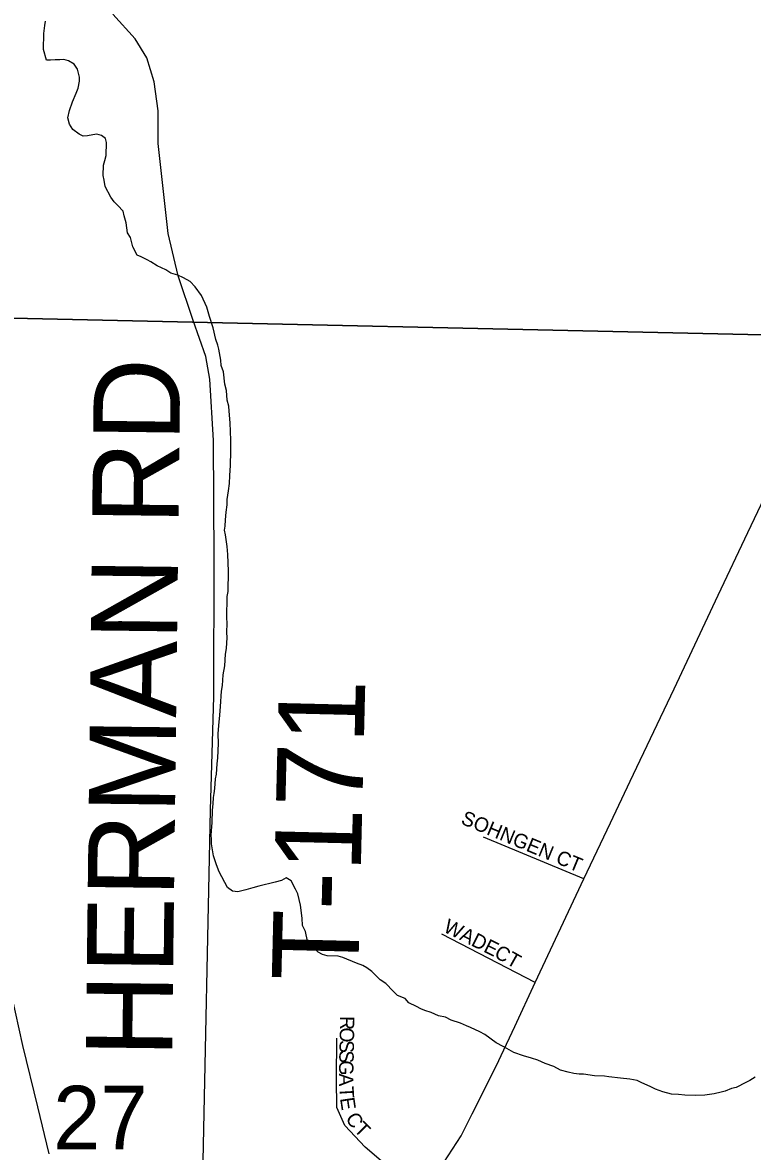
# Model space of a CAD drawing. Extents: x 0 to 34, y -2.3 to 22.
# Drawn here: x 5.852 to 6.332, y 15.821 to 16.564 of the extents above; entities that cross this region are included whole.
import ezdxf

# ---------------------------------------------------------------- set-up
doc = ezdxf.new("R2010")
doc.units = 0
for name, color, linetype in [('GM_X_Minor_River', 7, 'Continuous'), ('GM_X_Section', 7, 'Continuous'), ('GM_X_Section_Text', 7, 'Continuous'), ('GM_X_State_Route', 7, 'Continuous'), ('GM_X_Township_Road', 7, 'Continuous'), ('GM_X_Township_Road_Text', 7, 'Continuous'), ('GM_X_Township_Subdivision', 7, 'Continuous'), ('GM_X_Township_Subdivision_Text', 7, 'Continuous'), ('GM_X_US_Route', 7, 'Continuous')]:
    doc.layers.add(name, color=color, linetype=linetype)

msp = doc.modelspace()

# ---------------------------------------------------------------- linework, layer by layer
at = {"layer": 'GM_X_Minor_River'}
for p, q in [((5.86615, 16.56212), (5.86661, 16.56477)), ((5.86531, 16.54619), (5.86562, 16.55682)), ((5.86562, 16.55682), (5.86615, 16.56212)), ((5.86739, 16.53929), (5.86531, 16.54619)), ((5.87005, 16.53921), (5.86739, 16.53929)), ((5.8731, 16.5395), (5.87005, 16.53921)), ((5.87613, 16.53941), (5.8731, 16.5395)), ((5.8788, 16.53971), (5.87613, 16.53941)), ((5.88182, 16.53886), (5.8788, 16.53971)), ((5.88555, 16.53647), (5.88182, 16.53886)), ((5.88774, 16.53336), (5.88555, 16.53647)), ((5.88911, 16.52801), (5.88774, 16.53336)), ((5.88903, 16.52535), (5.88911, 16.52801)), ((5.8869, 16.51743), (5.88814, 16.52082)), ((5.88814, 16.52082), (5.88903, 16.52535)), ((5.88445, 16.51181), (5.8869, 16.51743)), ((5.88148, 16.50126), (5.88239, 16.50617)), ((5.88239, 16.50617), (5.88445, 16.51181)), ((5.8825, 16.49706), (5.88148, 16.50126)), ((5.88468, 16.49357), (5.8825, 16.49706)), ((5.88877, 16.49041), (5.88468, 16.49357)), ((5.89139, 16.48919), (5.88877, 16.49041)), ((5.89788, 16.49014), (5.89444, 16.48948)), ((5.90055, 16.49044), (5.89788, 16.49014)), ((5.90357, 16.48959), (5.90055, 16.49044)), ((5.89444, 16.48948), (5.89139, 16.48919)), ((5.90617, 16.48761), (5.90357, 16.48959)), ((5.90686, 16.48493), (5.90617, 16.48761)), ((5.90661, 16.47658), (5.90686, 16.48493)), ((5.90575, 16.47319), (5.90661, 16.47658)), ((5.90471, 16.46334), (5.90491, 16.47017)), ((5.90491, 16.47017), (5.90575, 16.47319)), ((5.90538, 16.46028), (5.90471, 16.46334)), ((5.90601, 16.45609), (5.90538, 16.46028)), ((5.90961, 16.44914), (5.90601, 16.45609)), ((5.9118, 16.44603), (5.90961, 16.44914)), ((5.9144, 16.44368), (5.9118, 16.44603)), ((5.91771, 16.43978), (5.9144, 16.44368)), ((5.91838, 16.43672), (5.91771, 16.43978)), ((5.91976, 16.43212), (5.91838, 16.43672)), ((5.92071, 16.42564), (5.91976, 16.43212)), ((5.92253, 16.42254), (5.92071, 16.42564)), ((5.92425, 16.41641), (5.92253, 16.42254)), ((5.92713, 16.41101), (5.92425, 16.41641)), ((5.92975, 16.40979), (5.92713, 16.41101)), ((5.9335, 16.40778), (5.92975, 16.40979)), ((5.93612, 16.40656), (5.9335, 16.40778)), ((5.94022, 16.40378), (5.93612, 16.40656)), ((5.94585, 16.40133), (5.94022, 16.40378)), ((5.94921, 16.39895), (5.94585, 16.40133)), ((5.95373, 16.39768), (5.94921, 16.39895)), ((5.95748, 16.39605), (5.95373, 16.39768)), ((5.96197, 16.39363), (5.95748, 16.39605)), ((5.96529, 16.39011), (5.96197, 16.39363)), ((5.9693, 16.3843), (5.96529, 16.39011)), ((5.97288, 16.37659), (5.9693, 16.3843)), ((5.9746, 16.37046), (5.97288, 16.37659)), ((5.97705, 16.36317), (5.9746, 16.37046)), ((5.97873, 16.35552), (5.97705, 16.36317)), ((5.98014, 16.35168), (5.97873, 16.35552)), ((5.98082, 16.349), (5.98014, 16.35168)), ((5.98213, 16.34175), (5.98082, 16.349)), ((5.98241, 16.33832), (5.98213, 16.34175)), ((5.98381, 16.3341), (5.98241, 16.33832)), ((5.98471, 16.32609), (5.98381, 16.3341)), ((5.98573, 16.32189), (5.98471, 16.32609)), ((5.9863, 16.31541), (5.98573, 16.32189)), ((5.98733, 16.31158), (5.9863, 16.31541)), ((5.98761, 16.30815), (5.98733, 16.31158)), ((5.98815, 16.30054), (5.98761, 16.30815)), ((5.98858, 16.28913), (5.98815, 16.30054)), ((5.98875, 16.28191), (5.98858, 16.28913)), ((5.98847, 16.27242), (5.98875, 16.28191)), ((5.98791, 16.26598), (5.98847, 16.27242)), ((5.98723, 16.25574), (5.98775, 16.26067)), ((5.98775, 16.26067), (5.98791, 16.26598)), ((5.98631, 16.25007), (5.98723, 16.25574)), ((5.98568, 16.24173), (5.98621, 16.24666)), ((5.98621, 16.24666), (5.98631, 16.25007)), ((5.98516, 16.23681), (5.98568, 16.24173)), ((5.98458, 16.22999), (5.98504, 16.23264)), ((5.98525, 16.22693), (5.98458, 16.22999)), ((5.98504, 16.23264), (5.98516, 16.23681)), ((5.98617, 16.21931), (5.98525, 16.22693)), ((5.98678, 16.21397), (5.98617, 16.21931)), ((5.98721, 16.20294), (5.98678, 16.21397)), ((5.98683, 16.18966), (5.98721, 16.20294)), ((5.98594, 16.17221), (5.98635, 16.18625)), ((5.98635, 16.18625), (5.98683, 16.18966)), ((5.98622, 16.16878), (5.98594, 16.17221)), ((5.98604, 16.16271), (5.98622, 16.16878)), ((5.98574, 16.15208), (5.98632, 16.15928)), ((5.98632, 16.15928), (5.98604, 16.16271)), ((5.98464, 16.14072), (5.98525, 16.1483)), ((5.98525, 16.1483), (5.98574, 16.15208)), ((5.98371, 16.13467), (5.98464, 16.14072)), ((5.98313, 16.12785), (5.98371, 16.13467)), ((5.98264, 16.12407), (5.98313, 16.12785)), ((5.98196, 16.11383), (5.98264, 16.12407)), ((5.98142, 16.10815), (5.98196, 16.11383)), ((5.98084, 16.10133), (5.98142, 16.10815)), ((5.9803, 16.09602), (5.98084, 16.10133)), ((5.9805, 16.08956), (5.9803, 16.09602)), ((5.98022, 16.08007), (5.9805, 16.08956)), ((5.97915, 16.06947), (5.97973, 16.07629)), ((5.97973, 16.07629), (5.98022, 16.08007)), ((5.97812, 16.06), (5.97869, 16.06644)), ((5.97869, 16.06644), (5.97915, 16.06947)), ((5.97764, 16.0566), (5.97812, 16.06)), ((5.97706, 16.04978), (5.97718, 16.05395)), ((5.97718, 16.05395), (5.97764, 16.0566)), ((5.97633, 16.03764), (5.97656, 16.04561)), ((5.97656, 16.04561), (5.97706, 16.04978)), ((5.97571, 16.02931), (5.97633, 16.03764)), ((5.97601, 16.02664), (5.97571, 16.02931)), ((5.97592, 16.0236), (5.97601, 16.02664)), ((5.97721, 16.01558), (5.97592, 16.0236)), ((5.97932, 16.00982), (5.97721, 16.01558)), ((5.98109, 16.00521), (5.97932, 16.00982)), ((5.98649, 15.99479), (5.98109, 16.00521)), ((6.02197, 15.99943), (6.01776, 15.99842)), ((6.02507, 16.00124), (6.02197, 15.99943)), ((6.02843, 15.99924), (6.02507, 16.00124)), ((5.98984, 15.99241), (5.98649, 15.99479)), ((5.99325, 15.99193), (5.98984, 15.99241)), ((5.99861, 15.99329), (5.99325, 15.99193)), ((6.00321, 15.99467), (5.99861, 15.99329)), ((6.00704, 15.9957), (6.00321, 15.99467)), ((6.01776, 15.99842), (6.00704, 15.9957)), ((6.03131, 15.99383), (6.02843, 15.99924)), ((6.03274, 15.99075), (6.03131, 15.99383)), ((6.03442, 15.9831), (6.03274, 15.99075)), ((6.0357, 15.97471), (6.03442, 15.9831)), ((6.03593, 15.96976), (6.0357, 15.97471)), ((6.03772, 15.96591), (6.03593, 15.96976)), ((6.03906, 15.95941), (6.03772, 15.96591)), ((6.04237, 15.95589), (6.03906, 15.95941)), ((6.04607, 15.95236), (6.04237, 15.95589)), ((6.04907, 15.95075), (6.04607, 15.95236)), ((6.05208, 15.9499), (6.04907, 15.95075)), ((6.0593, 15.94969), (6.05208, 15.9499)), ((6.06232, 15.94884), (6.0593, 15.94969)), ((6.07133, 15.94515), (6.06232, 15.94884)), ((6.07546, 15.9435), (6.07133, 15.94515)), ((6.07808, 15.94191), (6.07546, 15.9435)), ((6.08143, 15.93953), (6.07808, 15.94191)), ((6.08697, 15.93404), (6.08143, 15.93953)), ((6.0907, 15.93165), (6.08697, 15.93404)), ((6.0955, 15.92657), (6.0907, 15.93165)), ((6.09846, 15.92382), (6.0955, 15.92657)), ((6.10334, 15.92178), (6.09846, 15.92382)), ((6.10592, 15.91904), (6.10334, 15.92178)), ((6.11079, 15.91662), (6.10592, 15.91904)), ((6.11379, 15.91501), (6.11079, 15.91662)), ((6.11641, 15.91379), (6.11379, 15.91501)), ((6.12056, 15.91252), (6.11641, 15.91379)), ((6.12544, 15.91048), (6.12056, 15.91252)), ((6.12997, 15.90958), (6.12544, 15.91048)), ((6.13372, 15.90757), (6.12997, 15.90958)), ((6.13974, 15.90549), (6.13372, 15.90757)), ((6.14387, 15.90385), (6.13974, 15.90549)), ((6.1465, 15.90263), (6.14387, 15.90385)), ((6.1525, 15.89979), (6.1465, 15.90263)), ((6.15587, 15.89817), (6.1525, 15.89979)), ((6.16331, 15.89263), (6.15587, 15.89817)), ((6.1678, 15.89022), (6.16331, 15.89263)), ((6.17043, 15.889), (6.1678, 15.89022)), ((6.17491, 15.88621), (6.17043, 15.889)), ((6.18131, 15.88411), (6.17491, 15.88621)), ((6.18658, 15.88244), (6.18131, 15.88411)), ((6.19073, 15.88117), (6.18658, 15.88244)), ((6.19561, 15.87913), (6.19073, 15.88117)), ((6.20125, 15.87706), (6.19561, 15.87913)), ((6.20574, 15.87464), (6.20125, 15.87706)), ((6.21065, 15.87336), (6.20574, 15.87464)), ((6.21442, 15.87249), (6.21065, 15.87336)), ((6.21783, 15.872), (6.21442, 15.87249)), ((6.22087, 15.87191), (6.21783, 15.872)), ((6.22806, 15.87094), (6.22087, 15.87191)), ((6.23452, 15.87075), (6.22806, 15.87094)), ((6.23754, 15.87028), (6.23452, 15.87075)), ((6.24512, 15.86929), (6.23754, 15.87028)), ((6.25118, 15.86873), (6.24512, 15.86929)), ((6.2561, 15.86782), (6.25118, 15.86873)), ((6.25872, 15.8666), (6.2561, 15.86782)), ((6.2651, 15.86375), (6.25872, 15.8666)), ((6.32752, 15.86644), (6.32134, 15.86321)), ((6.33022, 15.86788), (6.32752, 15.86644)), ((6.3337, 15.87006), (6.33022, 15.86788)), ((6.2681, 15.86214), (6.2651, 15.86375)), ((6.27299, 15.86048), (6.2681, 15.86214)), ((6.27864, 15.85879), (6.27299, 15.86048)), ((6.2832, 15.85865), (6.27864, 15.85879)), ((6.28737, 15.85815), (6.2832, 15.85865)), ((6.30678, 15.85908), (6.30067, 15.85813)), ((6.31137, 15.86009), (6.30678, 15.85908)), ((6.31405, 15.86077), (6.31137, 15.86009)), ((6.31828, 15.86254), (6.31405, 15.86077)), ((6.32134, 15.86321), (6.31828, 15.86254)), ((6.2942, 15.85794), (6.28737, 15.85815)), ((6.30067, 15.85813), (6.2942, 15.85794))]:
    msp.add_line(p, q, dxfattribs=at)
at = {"layer": 'GM_X_Section'}
for p, q in [((6.52343, 16.35426), (5.31637, 16.38127)), ((5.31637, 16.38127), (6.52343, 16.35426))]:
    msp.add_line(p, q, dxfattribs=at)
at = {"layer": 'GM_X_State_Route'}
for p, q in [((6.32885, 16.22841), (6.35849, 16.29061)), ((6.30932, 16.18722), (6.32885, 16.22841)), ((6.2805, 16.12551), (6.30932, 16.18722)), ((6.25152, 16.06478), (6.2805, 16.12551)), ((6.23865, 16.03742), (6.25152, 16.06478)), ((6.22107, 16.00046), (6.23865, 16.03742)), ((6.18899, 15.9324), (6.22107, 16.00046)), ((6.17548, 15.90326), (6.18899, 15.9324)), ((6.16658, 15.88438), (6.17548, 15.90326)), ((6.16343, 15.87769), (6.16658, 15.88438)), ((6.14748, 15.84594), (6.16343, 15.87769)), ((6.14031, 15.83145), (6.14748, 15.84594)), ((6.12891, 15.81387), (6.14031, 15.83145))]:
    msp.add_line(p, q, dxfattribs=at)
at = {"layer": 'GM_X_Township_Road'}
for p, q in [((5.92576, 16.55322), (5.91112, 16.56944)), ((5.93334, 16.5407), (5.92576, 16.55322)), ((5.93827, 16.52501), (5.93334, 16.5407)), ((5.94092, 16.50597), (5.93827, 16.52501)), ((5.94074, 16.48429), (5.94092, 16.50597)), ((5.94744, 16.42506), (5.94074, 16.48429)), ((5.95396, 16.39721), (5.94744, 16.42506)), ((5.96384, 16.36794), (5.95396, 16.39721)), ((5.97212, 16.34414), (5.96384, 16.36794)), ((5.97477, 16.32934), (5.97212, 16.34414)), ((5.97723, 16.28897), (5.97477, 16.32934)), ((5.97776, 16.21034), (5.97723, 16.28897)), ((5.97759, 16.12061), (5.97776, 16.21034)), ((5.97529, 16.04569), (5.97759, 16.12061)), ((5.9696, 15.77502), (5.97529, 16.04569))]:
    msp.add_line(p, q, dxfattribs=at)
at = {"layer": 'GM_X_Township_Subdivision'}
for p, q in [((6.22107, 16.00046), (6.15496, 16.02798)), ((6.18899, 15.9324), (6.1275, 15.96418)), ((6.05825, 15.86874), (6.05843, 15.89568)), ((6.05841, 15.85017), (6.05825, 15.86874)), ((6.06362, 15.83813), (6.05841, 15.85017)), ((6.07714, 15.82396), (6.06362, 15.83813)), ((6.11275, 15.79357), (6.07714, 15.82396))]:
    msp.add_line(p, q, dxfattribs=at)
at = {"layer": 'GM_X_US_Route'}
for p, q in [((5.85172, 15.89091), (5.84202, 15.9348)), ((5.86176, 15.85054), (5.85172, 15.89091)), ((5.86917, 15.81951), (5.86176, 15.85054))]:
    msp.add_line(p, q, dxfattribs=at)

# ---------------------------------------------------------------- texts
at = {"layer": 'GM_X_Section_Text'}
msp.add_text('27', height=0.041856, rotation=0.00001, dxfattribs=at).set_placement((5.87172, 15.82248))
at = {"layer": 'GM_X_Township_Road_Text'}
for s, rotation, p in [('HERMAN RD', 89.31802, (5.95, 15.88274)), ('T-171', 88.61238, (6.07241, 15.93289))]:
    msp.add_text(s, height=0.056818, rotation=rotation, dxfattribs=at).set_placement(p)
at = {"layer": 'GM_X_Township_Subdivision_Text'}
for s, rotation, p in [('SOHNGEN CT', 337.47914, (6.13949, 16.03699)), ('WADE', 333.4361, (6.12793, 15.9661)), ('CT', 330.63982, (6.16134, 15.94939)), ('R', 268.87681, (6.06059, 15.9103)), ('O', 268.88362, (6.06044, 15.9028)), ('S', 268.88001, (6.06028, 15.89447)), ('S', 268.8728, (6.06015, 15.88781)), ('G', 268.88362, (6.06001, 15.88114)), ('A', 270.85745, (6.05985, 15.87245)), ('T', 273.53001, (6.05999, 15.86364)), ('E', 278.45801, (6.0605, 15.8561)), ('C', 302.26689, (6.0638, 15.84315)), ('T', 314.43494, (6.06917, 15.83509))]:
    msp.add_text(s, height=0.00947, rotation=rotation, dxfattribs=at).set_placement(p)

doc.saveas('drawing.dxf')
